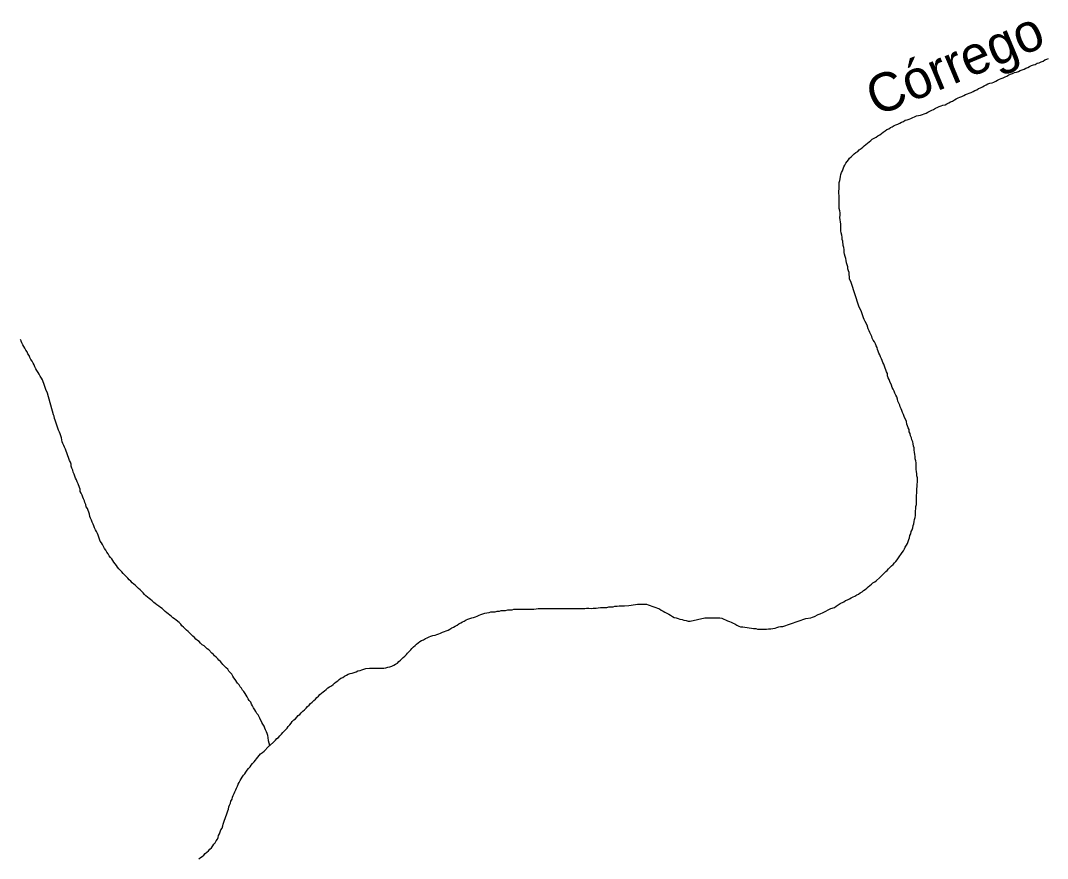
# Model space of a CAD drawing. Extents: x 785.9 to 812.4, y 7674.9 to 7703.1.
# Drawn here: x 798.512 to 801.186, y 7690.456 to 7692.637 of the extents above; entities that cross this region are included whole.
import ezdxf
from ezdxf.enums import TextEntityAlignment as Align

# ---------------------------------------------------------------- set-up
doc = ezdxf.new("R2010")
doc.units = 0
doc.header["$LTSCALE"] = 0.04
doc.layers.add('61', color=7, linetype='Continuous')
doc.layers.add('7', color=7, linetype='Continuous', lineweight=25)

msp = doc.modelspace()

# ---------------------------------------------------------------- linework, layer by layer
at = {"layer": '7'}
msp.add_line((799.161, 7690.7504), (799.158, 7690.7621), dxfattribs=at)
for points in [[(800.86, 7692.3928), (800.8649, 7692.3944), (800.8697, 7692.396), (800.8746, 7692.3984), (800.8794, 7692.4008), (800.8843, 7692.4041), (800.8891, 7692.4057), (800.894, 7692.4089), (800.8989, 7692.4106), (800.9037, 7692.413), (800.9086, 7692.4154), (800.9134, 7692.417), (800.9191, 7692.4178), (800.9239, 7692.4203), (800.9288, 7692.4227), (800.9336, 7692.4251), (800.9385, 7692.4275), (800.9434, 7692.4308), (800.9482, 7692.4332), (800.9531, 7692.4356), (800.9579, 7692.4373), (800.9628, 7692.4397), (800.9676, 7692.4421), (800.9725, 7692.4445), (800.9773, 7692.4462), (800.9822, 7692.4478), (800.9871, 7692.4502), (800.9919, 7692.4526), (800.9968, 7692.4551), (801.0016, 7692.4567), (801.0065, 7692.4599), (801.0113, 7692.4623), (801.0162, 7692.4648), (801.021, 7692.4672), (801.0259, 7692.4696), (801.0307, 7692.472), (801.0356, 7692.4737), (801.0413, 7692.4753), (801.0461, 7692.4769), (801.051, 7692.4793), (801.0558, 7692.4818), (801.0607, 7692.4842), (801.0655, 7692.4858), (801.0704, 7692.4882), (801.0752, 7692.4907), (801.0801, 7692.4923), (801.085, 7692.4955), (801.0898, 7692.4979), (801.0947, 7692.4996), (801.0995, 7692.502), (801.1052, 7692.5028), (801.11, 7692.5044), (801.1149, 7692.5068), (801.1198, 7692.5085), (801.1246, 7692.5109), (801.1295, 7692.5133), (801.1343, 7692.5149), (801.1392, 7692.5174), (801.144, 7692.5198), (801.1489, 7692.5214), (801.1537, 7692.523), (801.1586, 7692.5263), (801.1643, 7692.5271), (801.1691, 7692.5295), (801.174, 7692.5311), (801.1788, 7692.5344), (801.1837, 7692.5368), (801.1885, 7692.5384)], [(800.695, 7691.8935), (800.6747, 7691.955), (800.6707, 7691.9647), (800.6707, 7691.9704), (800.6691, 7691.9752), (800.6691, 7691.9809), (800.6674, 7691.9858), (800.6658, 7691.9906), (800.6658, 7691.9963), (800.6642, 7692.0011), (800.6626, 7692.006), (800.6618, 7692.0125), (800.661, 7692.0181), (800.6593, 7692.023), (800.6577, 7692.0286), (800.6561, 7692.0335), (800.6561, 7692.0408), (800.6553, 7692.0464), (800.6537, 7692.0513), (800.6529, 7692.0626), (800.6513, 7692.0675), (800.6513, 7692.0731), (800.6504, 7692.0788), (800.6488, 7692.0845), (800.648, 7692.0901), (800.648, 7692.0958), (800.648, 7692.1015), (800.648, 7692.1071), (800.6472, 7692.1128), (800.6456, 7692.1185), (800.6448, 7692.1241), (800.6456, 7692.1306), (800.6456, 7692.1363), (800.6448, 7692.1419), (800.6432, 7692.1476), (800.6432, 7692.1532), (800.6432, 7692.1589), (800.6432, 7692.1646), (800.6432, 7692.1702), (800.6432, 7692.1759), (800.6432, 7692.1816), (800.6424, 7692.1872), (800.6424, 7692.1929), (800.6432, 7692.1986), (800.6432, 7692.2042), (800.6432, 7692.2099), (800.6432, 7692.2155), (800.6448, 7692.2204), (800.6464, 7692.2253), (800.6472, 7692.2309), (800.648, 7692.2366), (800.6496, 7692.2414), (800.6521, 7692.2463), (800.6537, 7692.2512), (800.6553, 7692.256), (800.6585, 7692.2609), (800.661, 7692.2657), (800.6642, 7692.2706), (800.6674, 7692.2746), (800.6707, 7692.2787), (800.6747, 7692.2827), (800.6788, 7692.2868), (800.6828, 7692.29), (800.6869, 7692.2932), (800.6917, 7692.2965), (800.6958, 7692.3005), (800.7006, 7692.3037), (800.7047, 7692.3078), (800.7087, 7692.311), (800.7128, 7692.3143), (800.7168, 7692.3183), (800.7217, 7692.3215), (800.7257, 7692.3248), (800.7297, 7692.328), (800.7346, 7692.3313), (800.7395, 7692.3337), (800.7443, 7692.3369), (800.7492, 7692.3393), (800.7532, 7692.3434), (800.7581, 7692.3466), (800.7629, 7692.3499), (800.7678, 7692.3531), (800.7726, 7692.3555), (800.7767, 7692.3588), (800.7815, 7692.3604), (800.7864, 7692.3636), (800.7912, 7692.366), (800.7961, 7692.3677), (800.8009, 7692.3701), (800.8058, 7692.3725), (800.8107, 7692.3741), (800.8155, 7692.3774), (800.8204, 7692.379), (800.8252, 7692.3806), (800.8301, 7692.3822), (800.8349, 7692.3847), (800.8398, 7692.3863), (800.8446, 7692.3887), (800.8495, 7692.3903), (800.8552, 7692.3911), (800.86, 7692.3928)], [(800.8277, 7691.2964), (800.8301, 7691.3012), (800.8309, 7691.3069), (800.8333, 7691.3117), (800.8349, 7691.3166), (800.8357, 7691.3223), (800.8374, 7691.3271), (800.839, 7691.3328), (800.8398, 7691.3384), (800.8414, 7691.3433), (800.8422, 7691.349), (800.8422, 7691.3603), (800.843, 7691.3668), (800.843, 7691.3724), (800.8446, 7691.3773), (800.8446, 7691.4016), (800.8455, 7691.4072), (800.8455, 7691.4185), (800.8463, 7691.4242), (800.8463, 7691.4299), (800.8471, 7691.4355), (800.8471, 7691.4469), (800.8455, 7691.4517), (800.8455, 7691.4574), (800.8446, 7691.463), (800.8438, 7691.4687), (800.8438, 7691.4857), (800.843, 7691.4914), (800.8414, 7691.4962), (800.8414, 7691.5019), (800.8406, 7691.5075), (800.8398, 7691.5132), (800.839, 7691.5189), (800.839, 7691.5245), (800.8366, 7691.5294), (800.8357, 7691.5351), (800.8349, 7691.5407), (800.8325, 7691.5456), (800.8317, 7691.5512), (800.8293, 7691.5561), (800.8285, 7691.5618), (800.826, 7691.5666), (800.8252, 7691.5723), (800.8228, 7691.5771), (800.8212, 7691.582), (800.8196, 7691.5868), (800.8187, 7691.5933), (800.8123, 7691.6063), (800.8107, 7691.6119), (800.8082, 7691.6168), (800.8066, 7691.6216), (800.805, 7691.6265), (800.8026, 7691.6313), (800.8009, 7691.6362), (800.7985, 7691.6411), (800.7961, 7691.6459), (800.7953, 7691.6516), (800.7937, 7691.6572), (800.7912, 7691.6621), (800.788, 7691.6669), (800.7864, 7691.6726), (800.784, 7691.6775), (800.7815, 7691.6823), (800.7799, 7691.688), (800.7751, 7691.6977), (800.7734, 7691.7026), (800.771, 7691.7074), (800.7694, 7691.7123), (800.7694, 7691.7179), (800.767, 7691.7228), (800.7645, 7691.7276), (800.7629, 7691.7325), (800.7613, 7691.7373), (800.7597, 7691.7422), (800.7573, 7691.7471), (800.7556, 7691.7519), (800.7532, 7691.7568), (800.7508, 7691.7616), (800.7492, 7691.7665), (800.7467, 7691.7713), (800.7451, 7691.7762), (800.7435, 7691.781), (800.7419, 7691.7859), (800.7395, 7691.7907), (800.7378, 7691.7956), (800.7354, 7691.8005), (800.7322, 7691.8053), (800.7297, 7691.8102), (800.7281, 7691.815), (800.7257, 7691.8199), (800.7233, 7691.8247), (800.7217, 7691.8296), (800.7192, 7691.8344), (800.716, 7691.8442), (800.7111, 7691.8539), (800.7087, 7691.8587), (800.7071, 7691.8636), (800.7047, 7691.8684), (800.703, 7691.8733), (800.7014, 7691.8789), (800.695, 7691.8935)], [(798.5985, 7691.6103), (798.5823, 7691.6669), (798.5782, 7691.6767), (798.5766, 7691.6815), (798.575, 7691.6872), (798.5734, 7691.692), (798.5709, 7691.6969), (798.5693, 7691.7017), (798.5669, 7691.7066), (798.5637, 7691.7115), (798.5612, 7691.7163), (798.558, 7691.7212), (798.5548, 7691.726), (798.5523, 7691.7309), (798.5499, 7691.7357), (798.5475, 7691.7406), (798.5451, 7691.7454), (798.5426, 7691.7503), (798.5394, 7691.7551), (798.537, 7691.76), (798.5345, 7691.7649), (798.5313, 7691.7697), (798.5297, 7691.7746), (798.5264, 7691.7794), (798.524, 7691.7843), (798.5208, 7691.7883), (798.5184, 7691.7932), (798.5159, 7691.798), (798.5143, 7691.8021), (798.5137, 7691.8036), (798.5131, 7691.8051), (798.5125, 7691.8066), (798.5124, 7691.807)], [(798.7757, 7691.2017), (798.7724, 7691.2057), (798.7684, 7691.2098), (798.7651, 7691.2138), (798.7619, 7691.2187), (798.7587, 7691.2227), (798.7554, 7691.2268), (798.753, 7691.2316), (798.7498, 7691.2357), (798.7465, 7691.2397), (798.7433, 7691.2438), (798.7401, 7691.2486), (798.7368, 7691.2535), (798.7344, 7691.2583), (798.7312, 7691.2632), (798.7287, 7691.268), (798.7255, 7691.2729), (798.7231, 7691.2778), (798.7198, 7691.2818), (798.7182, 7691.2867), (798.7166, 7691.2923), (798.7142, 7691.2972), (798.7125, 7691.302), (798.7101, 7691.3069), (798.7077, 7691.3117), (798.7053, 7691.3166), (798.7036, 7691.3214), (798.7012, 7691.3263), (798.6988, 7691.3312), (798.6972, 7691.3368), (798.6947, 7691.3417), (798.6931, 7691.3465), (798.6923, 7691.3522), (798.6899, 7691.357), (798.6883, 7691.3619), (798.6867, 7691.3668), (798.6834, 7691.3716), (798.6826, 7691.3773), (798.6802, 7691.3821), (798.6786, 7691.387), (798.6761, 7691.3918), (798.6745, 7691.3967), (798.6729, 7691.4016), (798.6705, 7691.4064), (798.668, 7691.4113), (798.6672, 7691.4169), (798.6656, 7691.4218), (798.6624, 7691.4315), (798.66, 7691.4363), (798.6583, 7691.4412), (798.6559, 7691.4461), (798.6535, 7691.4509), (798.6519, 7691.4566), (798.6494, 7691.4614), (798.6486, 7691.4671), (798.6462, 7691.4719), (798.6446, 7691.4768), (798.6438, 7691.4825), (798.6422, 7691.4873), (798.6397, 7691.4922), (798.6381, 7691.497), (798.6349, 7691.5067), (798.6333, 7691.5116), (798.6316, 7691.5164), (798.6292, 7691.5213), (798.6268, 7691.5262), (798.6252, 7691.531), (798.6227, 7691.5359), (798.6211, 7691.5407), (798.6195, 7691.5456), (798.6187, 7691.5512), (798.6171, 7691.5561), (798.6155, 7691.561), (798.6138, 7691.5658), (798.6114, 7691.5707), (798.6098, 7691.5763), (798.6074, 7691.5812), (798.6057, 7691.5868), (798.6025, 7691.5966), (798.6009, 7691.6014), (798.6001, 7691.6071), (798.5985, 7691.6103)], [(800.5566, 7691.0803), (800.5695, 7691.0827), (800.5744, 7691.0844), (800.5792, 7691.086), (800.589, 7691.0908), (800.5938, 7691.0925), (800.6019, 7691.0965), (800.6213, 7691.1062), (800.631, 7691.1094), (800.6359, 7691.1127), (800.6407, 7691.1159), (800.6456, 7691.1192), (800.6553, 7691.124), (800.6602, 7691.1273), (800.665, 7691.1289), (800.6699, 7691.1321), (800.6747, 7691.1345), (800.6796, 7691.137), (800.6844, 7691.1386), (800.6893, 7691.1418), (800.6941, 7691.1442), (800.6982, 7691.1475), (800.703, 7691.1499), (800.7071, 7691.1531), (800.7111, 7691.1564), (800.7152, 7691.1596), (800.7192, 7691.1629), (800.7233, 7691.1661), (800.7273, 7691.1701), (800.7314, 7691.1734), (800.7362, 7691.1758), (800.7403, 7691.1798), (800.7484, 7691.1863), (800.7524, 7691.1904), (800.7564, 7691.1944), (800.7605, 7691.1985), (800.7645, 7691.2025), (800.7686, 7691.2057), (800.7718, 7691.2098), (800.7759, 7691.2138), (800.7799, 7691.2179), (800.784, 7691.2211), (800.7872, 7691.2252), (800.7912, 7691.2292), (800.7945, 7691.2332), (800.7977, 7691.2381), (800.8074, 7691.2527), (800.8107, 7691.2567), (800.8131, 7691.2616), (800.8155, 7691.2664), (800.8187, 7691.2713), (800.8212, 7691.2761), (800.8244, 7691.2858), (800.8268, 7691.2907), (800.8277, 7691.2964)], [(799.158, 7690.7621), (799.1568, 7690.7704), (799.156, 7690.7761), (799.1543, 7690.7809), (799.1527, 7690.7858), (799.1503, 7690.7906), (799.1487, 7690.7955), (799.1463, 7690.8004), (799.143, 7690.8052), (799.1406, 7690.8101), (799.1354, 7690.8212), (799.1309, 7690.8295), (799.1276, 7690.8335), (799.1252, 7690.8384), (799.122, 7690.8432), (799.1187, 7690.8481), (799.1163, 7690.853), (799.1139, 7690.8578), (799.1115, 7690.8627), (799.1074, 7690.8667), (799.105, 7690.8716), (799.1026, 7690.8764), (799.1001, 7690.8813), (799.0969, 7690.8853), (799.0937, 7690.8902), (799.0904, 7690.8942), (799.0872, 7690.8991), (799.0839, 7690.9031), (799.0815, 7690.908), (799.0775, 7690.912), (799.071, 7690.9217), (799.0678, 7690.9258), (799.0653, 7690.9306), (799.0621, 7690.9355), (799.0589, 7690.9395), (799.0548, 7690.9436), (799.0516, 7690.9484), (799.0475, 7690.9525), (799.0394, 7690.9606), (799.0362, 7690.9646), (799.033, 7690.9687), (799.0289, 7690.9719), (799.0257, 7690.9759), (799.0216, 7690.98), (799.0176, 7690.9832), (799.0144, 7690.9873), (799.0103, 7690.9905), (799.0022, 7690.9986), (798.9982, 7691.0018), (798.9941, 7691.0059), (798.9901, 7691.0091), (798.9852, 7691.0124), (798.9812, 7691.0164), (798.9771, 7691.0204), (798.9731, 7691.0237), (798.969, 7691.0269), (798.965, 7691.031), (798.961, 7691.035), (798.9488, 7691.0471), (798.9448, 7691.0504), (798.9407, 7691.0536), (798.9367, 7691.0577), (798.9326, 7691.0617), (798.9294, 7691.0658), (798.9254, 7691.0698), (798.9173, 7691.0763), (798.9132, 7691.0795), (798.9092, 7691.0827), (798.9051, 7691.086), (798.897, 7691.0925), (798.893, 7691.0957), (798.8889, 7691.0989), (798.8849, 7691.103), (798.8809, 7691.1062), (798.8768, 7691.1094), (798.872, 7691.1127), (798.8671, 7691.1159), (798.8631, 7691.1192), (798.859, 7691.1224), (798.855, 7691.1264), (798.8509, 7691.1297), (798.8469, 7691.1329), (798.8428, 7691.1362), (798.8388, 7691.1394), (798.8355, 7691.1434), (798.8315, 7691.1475), (798.8274, 7691.1515), (798.8234, 7691.1548), (798.8194, 7691.1588), (798.8153, 7691.1629), (798.8113, 7691.1661), (798.8072, 7691.1701), (798.8032, 7691.1734), (798.7991, 7691.1774), (798.7951, 7691.1815), (798.7918, 7691.1855), (798.7838, 7691.1936), (798.7797, 7691.1976), (798.7757, 7691.2017)], [(800.0104, 7691.1078), (800.0161, 7691.1086), (800.0217, 7691.1094), (800.0274, 7691.1094), (800.0331, 7691.1094), (800.0387, 7691.1094), (800.0436, 7691.1111), (800.0493, 7691.1111), (800.0549, 7691.1111), (800.0598, 7691.1127), (800.0654, 7691.1127), (800.0711, 7691.1135), (800.0792, 7691.1135), (800.0849, 7691.1135), (800.0962, 7691.1143), (800.1018, 7691.1151), (800.1075, 7691.1159), (800.1132, 7691.1167), (800.1188, 7691.1175), (800.1245, 7691.1175), (800.1302, 7691.1175), (800.1358, 7691.1175), (800.1415, 7691.1175), (800.1464, 7691.1159), (800.1512, 7691.1143), (800.1561, 7691.1127), (800.1609, 7691.1111), (800.1658, 7691.1094), (800.1706, 7691.1078), (800.1755, 7691.1054), (800.1803, 7691.1022), (800.1852, 7691.0997), (800.19, 7691.0973), (800.1949, 7691.0941), (800.1998, 7691.0916), (800.2046, 7691.0892), (800.2095, 7691.086), (800.2143, 7691.0836), (800.2192, 7691.0819), (800.224, 7691.0803), (800.2289, 7691.0787), (800.2345, 7691.0779), (800.2394, 7691.0763), (800.2451, 7691.0755), (800.2499, 7691.0738), (800.2556, 7691.0738), (800.2936, 7691.0819), (800.2952, 7691.0819), (800.2969, 7691.0819), (800.2985, 7691.0819), (800.3001, 7691.0819), (800.3017, 7691.0819), (800.3033, 7691.0819), (800.3049, 7691.0819), (800.3066, 7691.0819), (800.3082, 7691.0819), (800.3098, 7691.0819), (800.3114, 7691.0819), (800.313, 7691.0819), (800.3147, 7691.0819), (800.3163, 7691.0819), (800.3179, 7691.0819), (800.3195, 7691.0819), (800.3211, 7691.0819), (800.3227, 7691.0819), (800.3244, 7691.0819), (800.326, 7691.0819), (800.3276, 7691.0819), (800.3325, 7691.0819), (800.3381, 7691.0811), (800.343, 7691.0787), (800.3478, 7691.0771), (800.3527, 7691.0747), (800.3575, 7691.073), (800.3624, 7691.0706), (800.3672, 7691.0682), (800.3721, 7691.0666), (800.377, 7691.0633), (800.3818, 7691.0609), (800.3867, 7691.0593), (800.3923, 7691.0585), (800.398, 7691.0577), (800.4037, 7691.0569), (800.4093, 7691.056), (800.415, 7691.0552), (800.4207, 7691.0544), (800.4263, 7691.0544), (800.4312, 7691.0528), (800.4368, 7691.0528), (800.4425, 7691.0528), (800.4482, 7691.0528), (800.4538, 7691.0528), (800.4595, 7691.0536), (800.4652, 7691.0536), (800.4708, 7691.0544), (800.4765, 7691.0552), (800.4813, 7691.0569), (800.4862, 7691.0585), (800.491, 7691.0601), (800.4967, 7691.0601), (800.5566, 7691.0803)], [(799.4974, 7690.9687), (799.5015, 7690.9719), (799.5047, 7690.9759), (799.5087, 7690.9792), (799.5128, 7690.9824), (799.5168, 7690.9865), (799.5201, 7690.9905), (799.5241, 7690.9946), (799.5282, 7690.9986), (799.5314, 7691.0026), (799.5354, 7691.0067), (799.5395, 7691.0107), (799.5435, 7691.014), (799.5476, 7691.0172), (799.5516, 7691.0204), (799.5565, 7691.0229), (799.5613, 7691.0253), (799.5662, 7691.0285), (799.5711, 7691.0302), (799.5759, 7691.0326), (799.5808, 7691.0342), (799.5856, 7691.0366), (799.5913, 7691.0374), (799.5961, 7691.0391), (799.601, 7691.0407), (799.6058, 7691.0423), (799.6107, 7691.0447), (799.6156, 7691.0471), (799.6204, 7691.0488), (799.6253, 7691.0504), (799.6301, 7691.0528), (799.635, 7691.056), (799.6398, 7691.0577), (799.6439, 7691.0609), (799.6487, 7691.0633), (799.6536, 7691.0666), (799.6584, 7691.069), (799.6625, 7691.0722), (799.6673, 7691.0738), (799.6722, 7691.0771), (799.677, 7691.0787), (799.6819, 7691.0803), (799.6868, 7691.0819), (799.6916, 7691.0836), (799.6965, 7691.0852), (799.7013, 7691.0868), (799.7062, 7691.0892), (799.711, 7691.0908), (799.7159, 7691.0925), (799.7207, 7691.0941), (799.7264, 7691.0949), (799.7321, 7691.0965), (799.7369, 7691.0981), (799.7426, 7691.0981), (799.7483, 7691.0981), (799.7531, 7691.0997), (799.7588, 7691.0997), (799.7636, 7691.1014), (799.7693, 7691.1014), (799.775, 7691.1014), (799.7806, 7691.103), (799.7863, 7691.103), (799.7919, 7691.103), (799.7968, 7691.1046), (799.8025, 7691.1046), (799.8081, 7691.1046), (799.8138, 7691.1046), (799.8195, 7691.1046), (799.8259, 7691.1046), (799.8316, 7691.1046), (799.8373, 7691.1046), (799.8429, 7691.1046), (799.8486, 7691.1046), (799.8543, 7691.1054), (799.8599, 7691.1062), (799.8656, 7691.1062), (799.8712, 7691.1062), (799.8769, 7691.1062), (799.8826, 7691.1062), (799.8882, 7691.1062), (799.8939, 7691.1062), (799.8996, 7691.1062), (799.9052, 7691.1062), (799.9109, 7691.1062), (799.9166, 7691.107), (799.9222, 7691.1062), (799.9279, 7691.1062), (799.9335, 7691.1062), (799.9392, 7691.1062), (799.9449, 7691.1062), (799.953, 7691.1062), (799.9586, 7691.1062), (799.9643, 7691.1062), (799.97, 7691.1062), (799.9756, 7691.1062), (799.9813, 7691.1062), (799.9861, 7691.1078), (799.9918, 7691.1078), (799.9975, 7691.107), (800.0031, 7691.1078), (800.0104, 7691.1078)], [(799.161, 7690.7504), (799.1721, 7690.7599), (799.1762, 7690.7639), (799.1794, 7690.768), (799.1835, 7690.7712), (799.1875, 7690.7753), (799.1916, 7690.7793), (799.1948, 7690.7834), (799.1988, 7690.7874), (799.2029, 7690.7915), (799.2061, 7690.7955), (799.2094, 7690.7995), (799.2134, 7690.8036), (799.2166, 7690.8084), (799.2199, 7690.8125), (799.2239, 7690.8165), (799.228, 7690.8198), (799.232, 7690.8238), (799.2353, 7690.8279), (799.2393, 7690.8311), (799.2433, 7690.8352), (799.2474, 7690.8392), (799.2514, 7690.8432), (799.2555, 7690.8473), (799.2595, 7690.8513), (799.2636, 7690.8554), (799.2676, 7690.8594), (799.2717, 7690.8627), (799.2757, 7690.8667), (799.2798, 7690.8708), (799.2838, 7690.8748), (799.2879, 7690.8788), (799.2919, 7690.8829), (799.2959, 7690.8861), (799.3, 7690.8894), (799.304, 7690.8926), (799.3081, 7690.8958), (799.3121, 7690.8999), (799.317, 7690.9031), (799.3218, 7690.9055), (799.3259, 7690.9088), (799.3299, 7690.912), (799.334, 7690.9153), (799.338, 7690.9185), (799.3421, 7690.9217), (799.3461, 7690.925), (799.351, 7690.9274), (799.3558, 7690.9306), (799.3607, 7690.9331), (799.3655, 7690.9355), (799.3704, 7690.9371), (799.376, 7690.9379), (799.3809, 7690.9403), (799.3858, 7690.942), (799.3906, 7690.9444), (799.3963, 7690.9452), (799.4011, 7690.9468), (799.406, 7690.9484), (799.4116, 7690.95), (799.4206, 7690.9509), (799.4262, 7690.9509), (799.4319, 7690.9509), (799.4375, 7690.9509), (799.4432, 7690.9509), (799.4489, 7690.9517), (799.4578, 7690.9517), (799.4634, 7690.9525), (799.4683, 7690.9541), (799.474, 7690.9549), (799.4788, 7690.9565), (799.4837, 7690.9589), (799.4885, 7690.9614), (799.4934, 7690.9646), (799.4974, 7690.9687)], [(799.1463, 7690.7356), (799.1463, 7690.7356), (799.1576, 7690.747), (799.1587, 7690.7481), (799.1599, 7690.7492), (799.161, 7690.7504)], [(798.9763, 7690.4549), (798.9812, 7690.4581), (798.9852, 7690.4613), (798.9893, 7690.4646), (798.9933, 7690.4686), (798.9974, 7690.4727), (799.0014, 7690.4759), (799.0055, 7690.4799), (799.0095, 7690.484), (799.0127, 7690.4888), (799.016, 7690.4929), (799.0192, 7690.4969), (799.0216, 7690.5018), (799.0249, 7690.5058), (799.0265, 7690.5107), (799.0281, 7690.5155), (799.0305, 7690.5204), (799.0322, 7690.5252), (799.0338, 7690.5301), (799.037, 7690.535), (799.0386, 7690.5406), (799.0403, 7690.5455), (799.0419, 7690.5503), (799.0435, 7690.5552), (799.0451, 7690.56), (799.0467, 7690.5649), (799.0483, 7690.5698), (799.05, 7690.5746), (799.0516, 7690.5795), (799.054, 7690.5843), (799.0548, 7690.59), (799.0564, 7690.5948), (799.0589, 7690.5997), (799.0597, 7690.6054), (799.0629, 7690.6102), (799.0645, 7690.6151), (799.0661, 7690.6199), (799.0686, 7690.6248), (799.0702, 7690.6296), (799.0726, 7690.6345), (799.0742, 7690.6393), (799.0775, 7690.6442), (799.0791, 7690.649), (799.0815, 7690.6539), (799.0839, 7690.6588), (799.0864, 7690.6636), (799.0896, 7690.6677), (799.0928, 7690.6725), (799.0961, 7690.6766), (799.0993, 7690.6806), (799.1026, 7690.6855), (799.1058, 7690.6903), (799.1098, 7690.6944), (799.1131, 7690.6992), (799.1163, 7690.7033), (799.1204, 7690.7073), (799.1236, 7690.7114), (799.1268, 7690.7154), (799.1301, 7690.7194), (799.1333, 7690.7243), (799.1373, 7690.7283), (799.1422, 7690.7316), (799.1463, 7690.7356)]]:
    msp.add_lwpolyline(points, dxfattribs=at)

# ---------------------------------------------------------------- texts
at = {"layer": '61'}
msp.add_text('Córrego', height=0.1, rotation=22.697, dxfattribs=at).set_placement((800.9632, 7692.4798), align=Align.CENTER)

doc.saveas('drawing.dxf')
